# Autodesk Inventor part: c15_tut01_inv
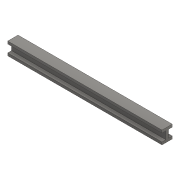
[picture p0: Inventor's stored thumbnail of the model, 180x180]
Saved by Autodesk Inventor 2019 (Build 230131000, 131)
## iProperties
Created: 2017-05
Part Number: c15_tut01_inv
Material: Steel, Alloy
Document SubType Name: Modeling
Designer: CADCIM 00
Mass: 637.725 g
Surface Area: 365.5 cm^2
Volume: 82.5 cm^3
Density: 7.73 g/cm^3
Appearance: Semi-Polished
Author: CADCIM 00
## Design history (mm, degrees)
sketch "Sketch1"
  geometry: L1 (-10, 25)-(10, 25); L2 (10, 25)-(10, 20); L3 (10, 20)-(2.5, 20); L4 (2.5, 20)-(2.5, 5); L5 (2.5, 5)-(10, 5); L6 (10, 5)-(10, 0); L7 (10, 0)-(-10, 0); L8 (-10, 0)-(-10, 5); L9 (-10, 5)-(-2.5, 5); L10 (-2.5, 5)-(-2.5, 20); L11 (-2.5, 20)-(-10, 20); L12 (-10, 25)-(-10, 20); 2 further points
  constraints: 24 end point, 8 perpendicular, 7 point on line, 2 collinear, 1 coincident, 1 horizontal, 1 midpoint
  dimensions: "d0" = 20 distance of L1.start L1.end; "d1" = 5 distance between parallel lines of L3 L1; "d2" = 15 distance between parallel lines of L5 L3; "d3" = 5 distance between parallel lines of L4 L10
extrude "Extrusion1" new body sketch "Sketch1" distance "d4" = 300; taper "d5" = 0 deg
body "Solid1"
other parameters: "sa_0" = 0, "sa_1" = 0, "sa_2" = -1000000
